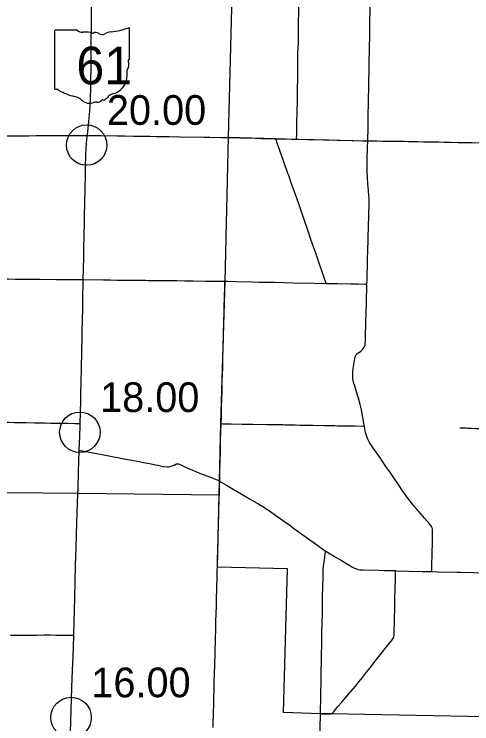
# Model space of a CAD drawing. Extents: x 1813937 to 1948437, y 826606 to 1022856.
# Drawn here: x 1876315 to 1893278, y 939932 to 966228 of the extents above; entities that cross this region are included whole.
import ezdxf

# ---------------------------------------------------------------- set-up
doc = ezdxf.new("R2010")
doc.units = 0
for name, color, linetype in [('Default', 7, 'Continuous'), ('GM_X_County_Road', 7, 'Continuous'), ('GM_X_State_Route', 7, 'Continuous'), ('GM_X_State_Shield', 7, 'Continuous'), ('GM_X_Township', 7, 'Continuous'), ('GM_X_Township_Road', 7, 'Continuous')]:
    doc.layers.add(name, color=color, linetype=linetype)

msp = doc.modelspace()

# ---------------------------------------------------------------- linework, layer by layer
at = {"layer": 'Default'}
for centre in [(1879002, 961378), (1878750, 950736), (1878424, 940166)]:
    msp.add_circle(centre, 750, dxfattribs=at)
at = {"layer": 'GM_X_County_Road'}
for points in [[(1889424, 961538), (1889434, 962041), (1889441, 962402), (1889451, 963025), (1889459, 963534), (1889476, 964387), (1889485, 964945), (1889494, 965470), (1889503, 965962), (1889509, 966356), (1889517, 966733), (1889520, 966850)], [(1873708, 961725), (1873925, 961725), (1874171, 961725), (1874400, 961725), (1874728, 961723), (1875040, 961721), (1875351, 961721), (1875696, 961724), (1876204, 961725), (1876483, 961726), (1876860, 961726), (1877139, 961727), (1877533, 961729), (1877959, 961730), (1878370, 961731), (1878730, 961731), (1878944, 961732), (1879031, 961735)], [(1879031, 961735), (1879064, 961735), (1879238, 961734), (1879550, 961729), (1880124, 961721), (1880403, 961717), (1880747, 961712), (1881174, 961704), (1881338, 961703), (1881584, 961698), (1881813, 961694), (1882059, 961692), (1882453, 961686), (1883355, 961673), (1883568, 961670), (1884011, 961664), (1884153, 961662)], [(1884153, 961662), (1884224, 961661), (1884683, 961649), (1884962, 961641), (1885257, 961632), (1885470, 961628), (1885683, 961622), (1885929, 961617), (1886003, 961615)], [(1886003, 961615), (1886142, 961612), (1886602, 961599), (1886785, 961597)], [(1886785, 961597), (1886848, 961596), (1887192, 961590), (1887438, 961582), (1887766, 961576), (1887979, 961573), (1888291, 961566), (1888832, 961553), (1889225, 961541), (1889305, 961540), (1889424, 961538)], [(1889391, 956223), (1889396, 956427), (1889399, 956591), (1889406, 956870), (1889414, 957214), (1889420, 957411), (1889433, 957936), (1889445, 958362), (1889457, 958772), (1889468, 959231), (1889469, 959411), (1889466, 959510), (1889452, 959690), (1889429, 959951), (1889412, 960180), (1889397, 960409), (1889393, 960540), (1889394, 960655), (1889402, 960901), (1889413, 961261), (1889424, 961538)], [(1889424, 961538), (1889576, 961533), (1889771, 961530), (1889984, 961529), (1890296, 961523), (1890476, 961521), (1890788, 961517), (1891263, 961507), (1891493, 961503), (1891870, 961495), (1892050, 961493), (1892247, 961490), (1892378, 961489), (1892476, 961487), (1892771, 961478), (1892902, 961475), (1892968, 961474), (1893050, 961473), (1893148, 961472), (1893279, 961470)], [(1889186, 951564), (1889176, 951616), (1889143, 951760), (1889078, 951997), (1889044, 952106), (1888991, 952278), (1888936, 952450), (1888897, 952576), (1888877, 952655), (1888867, 952720), (1888863, 952785), (1888863, 952866), (1888872, 952996), (1888883, 953094), (1888918, 953321), (1888945, 953466), (1888959, 953530), (1888975, 953576), (1888991, 953604), (1889010, 953630), (1889034, 953653), (1889072, 953683), (1889167, 953746), (1889205, 953777), (1889240, 953812), (1889269, 953851), (1889292, 953894), (1889310, 953940), (1889319, 953972), (1889326, 954020), (1889332, 954102), (1889336, 954217), (1889343, 954462), (1889347, 954626), (1889355, 954921), (1889358, 955052), (1889363, 955216), (1889370, 955445), (1889374, 955642), (1889376, 955739), (1889386, 956018), (1889391, 956223)], [(1889295, 950966), (1889276, 951068), (1889201, 951487), (1889186, 951564)], [(1891793, 945572), (1891794, 945623), (1891802, 945902), (1891808, 946148), (1891811, 946295), (1891812, 946393), (1891815, 946524), (1891820, 946688), (1891823, 946819), (1891826, 947032), (1891825, 947098), (1891818, 947146), (1891804, 947193), (1891783, 947238), (1891758, 947280), (1891709, 947345), (1891527, 947557), (1891387, 947718), (1891225, 947903), (1891107, 948039), (1891003, 948166), (1890904, 948297), (1890782, 948471), (1890690, 948607), (1890534, 948838), (1890441, 948973), (1890338, 949121), (1890263, 949229), (1890097, 949473), (1889864, 949810), (1889639, 950132), (1889538, 950281), (1889477, 950379), (1889439, 950452), (1889400, 950542), (1889362, 950650), (1889341, 950729), (1889312, 950874), (1889295, 950966)], [(1878728, 950072), (1878772, 950063), (1879110, 949997), (1879578, 949908), (1879949, 949836), (1880223, 949784), (1880384, 949754), (1880674, 949700), (1880932, 949650), (1881110, 949616), (1881335, 949574), (1881561, 949530), (1881851, 949473), (1881980, 949451), (1882013, 949449), (1882045, 949452), (1882093, 949464), (1882171, 949490), (1882246, 949522), (1882306, 949550), (1882337, 949560), (1882370, 949564), (1882402, 949562), (1882434, 949554), (1882494, 949527), (1882805, 949379), (1882957, 949317), (1883185, 949226), (1883629, 949054), (1883859, 948965), (1883918, 948938), (1883935, 948928)], [(1883920, 948423), (1883923, 948503), (1883924, 948585), (1883927, 948678), (1883930, 948781), (1883935, 948928)], [(1883935, 948928), (1884017, 948879), (1884184, 948775), (1884438, 948624), (1884664, 948490), (1885061, 948259), (1885389, 948072), (1885529, 947987), (1885774, 947821), (1886016, 947651), (1886256, 947481), (1886564, 947263), (1886671, 947186), (1886844, 947062), (1887017, 946936), (1887576, 946534), (1887803, 946372), (1887861, 946335)], [(1883841, 945540), (1883841, 945543), (1883843, 945641), (1883846, 945734), (1883847, 945803), (1883848, 945863), (1883849, 945901), (1883850, 945959), (1883852, 946010), (1883854, 946068), (1883856, 946113), (1883857, 946159), (1883858, 946235), (1883859, 946286), (1883861, 946382), (1883863, 946474), (1883864, 946519), (1883871, 946699), (1883877, 946847), (1883878, 946929), (1883881, 947060), (1883886, 947175), (1883889, 947306), (1883892, 947421), (1883897, 947585), (1883900, 947716), (1883907, 947978), (1883912, 948137), (1883915, 948257), (1883918, 948355), (1883920, 948423)], [(1887666, 940305), (1887671, 940493), (1887678, 940805), (1887685, 941133), (1887690, 941428), (1887692, 941674), (1887698, 941937), (1887702, 942183), (1887707, 942511), (1887713, 942839), (1887719, 943200), (1887723, 943414), (1887728, 943594), (1887739, 944119), (1887744, 944365), (1887749, 944644), (1887757, 945038), (1887762, 945300), (1887766, 945514), (1887773, 945661), (1887783, 945776), (1887824, 946101), (1887843, 946248), (1887853, 946296), (1887861, 946335)], [(1887861, 946335), (1887928, 946292), (1888194, 946131), (1888449, 945981), (1888689, 945839), (1888860, 945742), (1888933, 945704), (1889008, 945672), (1889071, 945653), (1889136, 945641), (1889234, 945634), (1889825, 945622), (1890038, 945616), (1890452, 945608)], [(1883690, 939792), (1883694, 939939), (1883697, 940021), (1883701, 940202), (1883705, 940398), (1883711, 940611), (1883714, 940759), (1883717, 940907), (1883723, 941136), (1883725, 941267), (1883732, 941464), (1883733, 941530), (1883734, 941584), (1883736, 941648), (1883738, 941714), (1883740, 941775), (1883744, 941906), (1883748, 942021), (1883752, 942169), (1883756, 942300), (1883759, 942382), (1883763, 942480), (1883767, 942610), (1883770, 942708), (1883775, 942905), (1883779, 943020), (1883780, 943101), (1883782, 943216), (1883784, 943314), (1883786, 943380), (1883788, 943478), (1883792, 943625), (1883795, 943724), (1883802, 944019), (1883809, 944297), (1883811, 944412), (1883819, 944675), (1883822, 944806), (1883826, 944953), (1883831, 945117), (1883833, 945215), (1883835, 945314), (1883837, 945412), (1883841, 945540)], [(1888096, 940316), (1888102, 940320), (1888126, 940342), (1888158, 940380), (1888305, 940557), (1888455, 940731), (1888585, 940879), (1888886, 941226), (1888971, 941326), (1889101, 941495), (1889223, 941650), (1889375, 941844), (1889508, 942011), (1889651, 942191), (1889834, 942423), (1889946, 942564), (1890108, 942770), (1890304, 943013), (1890353, 943079), (1890377, 943122), (1890389, 943153), (1890398, 943201), (1890402, 943266), (1890405, 943463), (1890409, 943611), (1890415, 943906), (1890419, 944136), (1890429, 944645), (1890433, 944875), (1890444, 945383), (1890449, 945548), (1890452, 945608)], [(1890452, 945608), (1890497, 945607), (1890956, 945594), (1891432, 945581), (1891793, 945572)], [(1891793, 945572), (1892006, 945566), (1892728, 945552), (1892876, 945549), (1893352, 945535), (1893729, 945524), (1894221, 945511), (1894434, 945507), (1894492, 945506)], [(1887613, 937674), (1887614, 937721), (1887621, 938130), (1887630, 938654), (1887634, 938932), (1887641, 939226), (1887666, 940305)], [(1887666, 940305), (1887714, 940305), (1887779, 940306), (1887943, 940298), (1888025, 940296), (1888058, 940300), (1888073, 940305), (1888088, 940311), (1888096, 940316)]]:
    msp.add_lwpolyline(points, dxfattribs=at)
at = {"layer": 'GM_X_State_Route'}
for points in [[(1879155, 963530), (1879156, 963565), (1879164, 964434), (1879170, 965041), (1879178, 965960), (1879189, 967078)], [(1879031, 961740), (1879088, 962255), (1879113, 962500), (1879134, 962794), (1879149, 963106), (1879155, 963530)], [(1878400, 939601), (1878426, 940454), (1878440, 940847), (1878456, 941290), (1878467, 941601), (1878478, 941912), (1878497, 942437), (1878511, 942797), (1878526, 943222), (1878527, 943240), (1878539, 943683), (1878550, 944142), (1878562, 944584), (1878578, 945207), (1878593, 945781), (1878604, 946142), (1878613, 946421), (1878630, 946961), (1878643, 947371), (1878654, 947732), (1878667, 948142), (1878676, 948404), (1878676, 948411), (1878685, 948699), (1878701, 949207), (1878717, 949716), (1878725, 949978), (1878728, 950072), (1878737, 950338), (1878745, 950568), (1878758, 950994), (1878760, 951058), (1878771, 951469), (1878781, 951895), (1878788, 952207), (1878795, 952568), (1878822, 953699), (1878835, 954257), (1878839, 954535), (1878845, 954781), (1878858, 955437), (1878865, 955798), (1878875, 956241), (1878878, 956392), (1878886, 956798), (1878895, 957208), (1878903, 957635), (1878910, 957979), (1878922, 958553), (1878927, 958815), (1878934, 959176), (1878945, 959766), (1878955, 960225), (1878960, 960521), (1878972, 961045), (1878980, 961242), (1878997, 961455), (1879026, 961692), (1879031, 961735), (1879031, 961740)]]:
    msp.add_lwpolyline(points, dxfattribs=at)
at = {"layer": 'GM_X_State_Shield'}
for p, q in [((1877810, 965595), (1877810, 963482)), ((1878653, 965631), (1877837, 965631)), ((1880594, 964578), (1880594, 965684)), ((1880594, 964579), (1880594, 964578))]:
    msp.add_line(p, q, dxfattribs=at)
for centre, radius, start, end in [((1877842, 965600), 32.3, 98.1301, 188.1301), ((1878847, 965877), 313, 231.6195, 271.1119), ((1879602, 968513), 2953, 275.8445, 288.9065), ((1880563, 965688), 31, 351.8621, 97.738), ((1878951, 964445), 1123, 80.4867, 94.9883), ((1879206, 965611), 90.3, 219.7921, 297.1024), ((1879338, 965366), 188, 54.4667, 119.1411), ((1879580, 965701), 226, 233.8562, 294.8282), ((1879979, 964986), 594, 97.3462, 120.7689), ((1880587, 964497), 48, 107.944, 210.337), ((1880561, 964574), 33.2, 289.6038, 7.7341), ((1880282, 964357), 288, 340.033, 23.6496), ((1879768, 963975), 739, 292.3089, 8.9858), ((1880705, 964116), 210, 136.8065, 186.9296), ((1877842, 963477), 32.5, 171.9584, 258.3066), ((1877847, 963693), 248, 267.339, 280.6039), ((1877898, 963360), 89.5, 29.7484, 93.2717), ((1879028, 965259), 2132, 240.4129, 257.1985), ((1880079, 962889), 404, 94.4031, 142.5768), ((1878393, 962532), 667, 47.1842, 75.836), ((1879114, 963349), 423, 230.7004, 286.2918), ((1879359, 962619), 348, 85.6951, 111.2099), ((1879390, 963191), 226, 268.777, 315.5493), ((1879594, 962987), 63.5, 65.7517, 132.6484), ((1879567, 963277), 239, 282.8732, 323.2771)]:
    msp.add_arc(centre, radius, start, end, dxfattribs=at)
at = {"layer": 'GM_X_Township'}
for points in [[(1884254, 961672), (1884396, 966955), (1884454, 969588), (1884489, 972257), (1884586, 977269), (1884741, 982824), (1884889, 988110)], [(1894401, 940177), (1888046, 940302), (1887975, 940298), (1887848, 940308), (1887664, 940306), (1886300, 940350), (1886440, 945673), (1883847, 945742), (1883913, 948407), (1883928, 948931), (1883977, 951060), (1884130, 956331), (1884254, 961672), (1886005, 961618), (1886788, 961599), (1889423, 961536), (1894728, 961453)], [(1883913, 948407), (1878685, 948461), (1873425, 948517), (1868265, 948533), (1868323, 950291)]]:
    msp.add_lwpolyline(points, dxfattribs=at)
at = {"layer": 'GM_X_Township_Road'}
for points in [[(1886785, 961597), (1886785, 961626), (1886789, 961756), (1886793, 961953), (1886797, 962182), (1886807, 962674), (1886811, 962985), (1886819, 963460), (1886826, 963852), (1886829, 964033), (1886828, 964697), (1886831, 964812), (1886842, 964956), (1886848, 965186), (1886852, 965497), (1886857, 965710), (1886859, 965923), (1886866, 966316), (1886870, 966513), (1886873, 966709), (1886874, 966824), (1886873, 966904)], [(1886426, 960438), (1886414, 960472), (1886364, 960611), (1886338, 960689), (1886289, 960828), (1886272, 960874), (1886067, 961446), (1886020, 961569), (1886003, 961615)], [(1887492, 957377), (1887423, 957572), (1887314, 957882), (1887195, 958223), (1887074, 958581), (1886953, 958939), (1886861, 959203), (1886755, 959514), (1886662, 959777), (1886600, 959946), (1886507, 960209), (1886452, 960364), (1886426, 960438)], [(1887877, 956253), (1887866, 956283), (1887807, 956454), (1887742, 956640), (1887658, 956889), (1887570, 957154), (1887492, 957377)], [(1873585, 956443), (1873607, 956443), (1873902, 956438), (1874132, 956437), (1874295, 956435), (1874656, 956432), (1875050, 956427), (1875362, 956426), (1875624, 956424), (1875887, 956422), (1876100, 956420), (1876346, 956415), (1876707, 956414), (1877281, 956410), (1877872, 956403), (1878429, 956399), (1878675, 956396), (1878872, 956392), (1878878, 956392)], [(1878878, 956392), (1879627, 956384), (1879873, 956382), (1880119, 956378), (1880660, 956372), (1880890, 956369), (1881185, 956366), (1881283, 956365), (1881463, 956364), (1881660, 956362), (1882086, 956357), (1882349, 956354), (1882644, 956350), (1882791, 956347), (1882955, 956346), (1883414, 956340), (1883677, 956337), (1883906, 956334), (1884022, 956333), (1884124, 956331)], [(1884029, 952612), (1884029, 952647), (1884035, 952876), (1884044, 953138), (1884049, 953335), (1884055, 953564), (1884063, 953793), (1884067, 953941), (1884070, 954121), (1884072, 954268), (1884077, 954481), (1884082, 954694), (1884087, 954874), (1884096, 955136), (1884099, 955251), (1884104, 955398), (1884112, 955709), (1884121, 956135), (1884124, 956299), (1884124, 956331)], [(1884124, 956331), (1884234, 956330), (1884530, 956323), (1885137, 956308), (1885399, 956304), (1885628, 956301), (1885957, 956294), (1886662, 956278), (1887416, 956263), (1887877, 956253)], [(1887877, 956253), (1887974, 956251), (1888302, 956248), (1888794, 956237), (1889072, 956232), (1889318, 956224), (1889391, 956223)], [(1883986, 951056), (1883994, 951320), (1883997, 951435), (1884001, 951615), (1884013, 952024), (1884020, 952237), (1884024, 952434), (1884029, 952612)], [(1873504, 951153), (1873578, 951153), (1874087, 951146), (1874382, 951144), (1874612, 951140), (1874923, 951136), (1875070, 951132), (1875218, 951127), (1875562, 951117), (1875726, 951113), (1875923, 951111), (1876119, 951107), (1876332, 951103), (1876562, 951098), (1876742, 951094), (1877070, 951089), (1877447, 951082), (1877661, 951079), (1877890, 951074), (1878038, 951071), (1878316, 951067), (1878562, 951062), (1878726, 951059), (1878760, 951058)], [(1883935, 948928), (1883938, 949076), (1883944, 949306), (1883954, 949716), (1883959, 949961), (1883963, 950125), (1883965, 950272), (1883966, 950469), (1883976, 950747), (1883986, 951056)], [(1883986, 951056), (1884045, 951054), (1884094, 951053), (1884356, 951049), (1884766, 951041), (1885160, 951034), (1885668, 951027), (1885767, 951024), (1885799, 951022), (1885962, 951020), (1886028, 951021), (1886110, 951024), (1886191, 951023), (1886272, 951019), (1886353, 951014), (1886419, 951012), (1886566, 951009), (1886730, 951006), (1886910, 951005), (1887025, 951004), (1887155, 951002), (1887270, 951001), (1887401, 950999), (1887794, 950992), (1887886, 950990)], [(1887886, 950990), (1888071, 950986), (1888202, 950984), (1888317, 950980), (1888497, 950975), (1888627, 950974), (1888939, 950971), (1889251, 950966), (1889295, 950966)], [(1892832, 950898), (1892960, 950896), (1893057, 950894), (1893067, 950894)], [(1893067, 950894), (1893114, 950893), (1893165, 950891), (1893180, 950890), (1893212, 950888), (1893266, 950887), (1893425, 950881), (1893622, 950877), (1893934, 950871), (1894114, 950866), (1894311, 950861), (1894557, 950855), (1894593, 950855)], [(1876183, 943223), (1876330, 943223), (1876494, 943223), (1876740, 943222), (1877019, 943222), (1877151, 943223), (1877413, 943224), (1877577, 943224), (1877659, 943224), (1877856, 943222), (1878119, 943222), (1878349, 943223), (1878430, 943223), (1878511, 943222), (1878526, 943222)]]:
    msp.add_lwpolyline(points, dxfattribs=at)

# ---------------------------------------------------------------- texts
at = {"layer": 'Default'}
for s, p in [('20.00', (1879752, 962128)), ('18.00', (1879500, 951486)), ('16.00', (1879174, 940916))]:
    msp.add_text(s, height=1100, dxfattribs=at).set_placement(p)
at = {"layer": 'GM_X_State_Shield'}
msp.add_text('61', height=1392.2, dxfattribs=at).set_placement((1878620, 963631))

doc.saveas('drawing.dxf')
